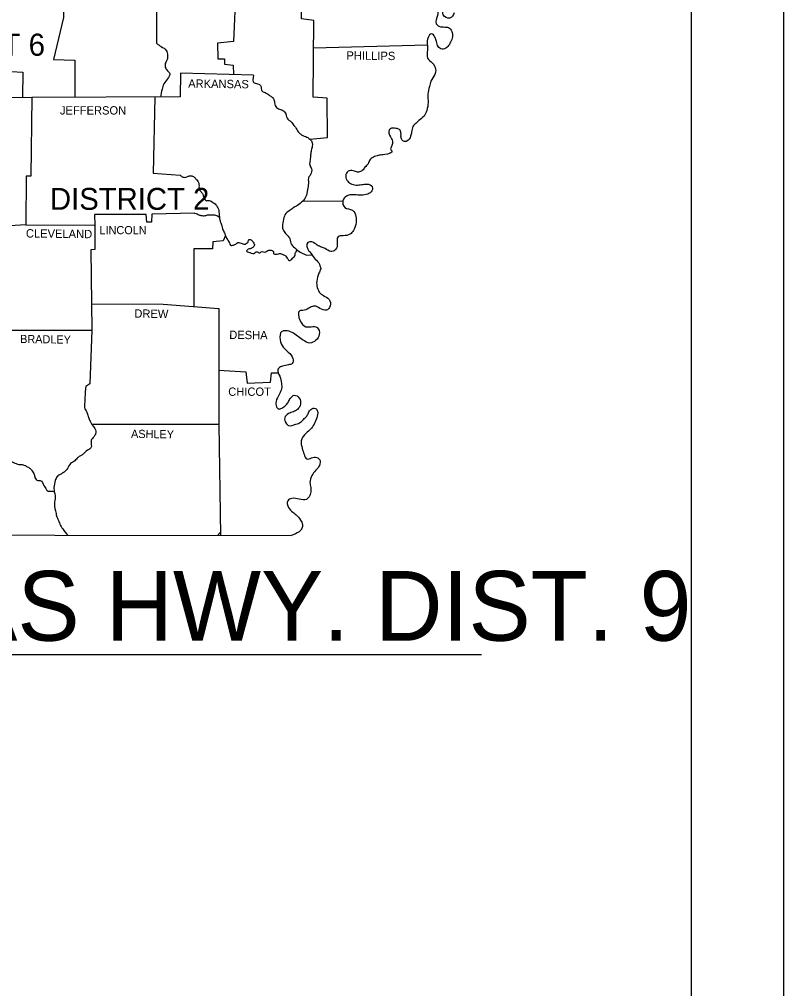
# Model space of a CAD drawing. Extents: x 19118 to 454486, y 1325406 to 1693506.
# Drawn here: x 26699 to 27093, y 1326542 to 1327042 of the extents above; entities that cross this region are included whole.
import ezdxf

# ---------------------------------------------------------------- set-up
doc = ezdxf.new("R2010")
doc.units = 0
for name, color, linetype in [('S_CURB', 7, 'Continuous'), ('S_EDGE_PAVEMENT', 7, 'Continuous'), ('S_SHOULDER', 7, 'Continuous')]:
    doc.layers.add(name, color=color, linetype=linetype)

msp = doc.modelspace()

# ---------------------------------------------------------------- linework, layer by layer
at = {"layer": 'S_CURB'}
for p, q in [((26844.86, 1326948.38), (26865.56, 1326948.58)), ((26435.93, 1326714.21), (26937.16, 1326714.21))]:
    msp.add_line(p, q, dxfattribs=at)
for points in [[(26754.87, 1327086.48), (26755.06, 1327068.58), (26769.16, 1327068.28), (26769.26, 1327029.88)], [(26715.37, 1327081.88), (26721.17, 1327081.48), (26721.27, 1327043.28), (26716.07, 1327021.58), (26727.17, 1327021.08), (26727.06, 1327001.97)], [(26848.46, 1326980.38), (26857.56, 1326981.18), (26857.46, 1327001.48), (26850.16, 1327001.98), (26850.56, 1327041.68), (26844.26, 1327042.58), (26844.06, 1327069.28), (26929.36, 1327069.88)], [(26810.26, 1327058.18), (26809.06, 1327030.78), (26800.86, 1327029.88), (26801.06, 1327021.78), (26804.36, 1327021.88), (26804.46, 1327019.08), (26808.96, 1327018.58), (26809.11, 1327013.76)], [(26638.17, 1327056.88), (26649.37, 1327056.18), (26648.97, 1327043.68), (26662.07, 1327043.18), (26662.27, 1327032.28), (26668.47, 1327031.78), (26668.47, 1327029.88), (26674.27, 1327029.48), (26674.47, 1327022.48), (26687.67, 1327022.48), (26688.07, 1327015.58), (26700.27, 1327014.98), (26700.17, 1327001.98)], [(26850.42, 1327027.58), (26909.17, 1327029.03)], [(26819.46, 1327013.48), (26781.66, 1327014.48), (26781.46, 1327002.18), (26704.97, 1327001.88)], [(26647.37, 1326988.68), (26652.97, 1326989.48), (26653.37, 1326992.88), (26656.67, 1326993.48), (26656.87, 1326995.48), (26680.17, 1326996.18), (26681.07, 1327002.28), (26704.97, 1327001.88)], [(26704.97, 1327001.88), (26704.37, 1326961.28), (26702.07, 1326961.18), (26701.77, 1326936.08)], [(26768.4, 1327002.13), (26767.56, 1326962.88), (26781.46, 1326961.78)], [(26788.87, 1326942.09), (26766.83, 1326941.55), (26766.66, 1326937.48), (26764.36, 1326937.48), (26763.96, 1326941.38), (26737.37, 1326941.38), (26737.4, 1326935.88)], [(26701.77, 1326936.08), (26687.93, 1326935.23)], [(26701.77, 1326936.08), (26737.17, 1326935.88)], [(26737.4, 1326935.88), (26737.47, 1326923.38), (26735.37, 1326923.28), (26735.97, 1326881.78)], [(26804.96, 1326930.58), (26803.76, 1326927.88), (26798.46, 1326927.38), (26798.16, 1326923.78), (26788.66, 1326923.78), (26788.56, 1326893.88)], [(26841.86, 1326923.18), (26843.54, 1326921.93), (26846.7, 1326920.44), (26849.49, 1326920.53)], [(26735.67, 1326895.38), (26772.76, 1326895.08), (26801.56, 1326892.88)], [(26801.56, 1326892.88), (26801.56, 1326833.09), (26802.36, 1326775.59)], [(26690.77, 1326881.68), (26735.97, 1326881.78)], [(26735.97, 1326881.78), (26734.97, 1326853.99), (26732.77, 1326852.59)], [(26801.56, 1326861.01), (26815.46, 1326860.19), (26816.06, 1326854.39), (26828.16, 1326854.79), (26828.66, 1326859.69), (26832.48, 1326859.68)], [(26472.17, 1326857.09), (26472.37, 1326776.19), (26838.86, 1326775.59)], [(26736.57, 1326833.19), (26801.56, 1326833.19)], [(26717.67, 1326805.69), (26718.47, 1326806.49)], [(26800.76, 1326775.69), (26802.26, 1326777.19)]]:
    msp.add_lwpolyline(points, dxfattribs=at)
for points in [[(26923.06, 1327045.68), (26920.76, 1327042.78), (26917.36, 1327044.58), (26917.36, 1327046.98), (26917.86, 1327049.48), (26916.66, 1327051.08), (26914.56, 1327050.38), (26914.56, 1327047.28), (26914.36, 1327044.28), (26913.76, 1327039.98), (26915.16, 1327038.68), (26918.36, 1327038.28), (26920.66, 1327037.68), (26922.06, 1327035.38), (26921.96, 1327032.58), (26920.86, 1327029.88), (26919.26, 1327027.68), (26916.76, 1327026.88), (26914.76, 1327028.18), (26913.96, 1327030.78), (26913.06, 1327033.08), (26911.36, 1327034.78), (26909.56, 1327032.88), (26909.16, 1327029.38), (26909.26, 1327026.38), (26909.26, 1327022.28), (26911.86, 1327019.58), (26913.46, 1327016.48), (26912.96, 1327013.68), (26911.06, 1327010.38), (26910.26, 1327007.48), (26909.46, 1327003.58), (26909.56, 1326999.28), (26908.86, 1326995.08), (26907.46, 1326992.28), (26904.86, 1326989.98), (26903.16, 1326988.48), (26901.76, 1326986.98), (26901.06, 1326983.98), (26900.56, 1326981.88), (26898.66, 1326979.38), (26897.16, 1326979.18), (26895.96, 1326980.18), (26895.56, 1326981.88), (26895.56, 1326983.58), (26894.76, 1326985.28), (26892.26, 1326985.98), (26890.26, 1326985.88), (26889.36, 1326984.48), (26890.66, 1326980.58), (26891.16, 1326978.08), (26890.46, 1326974.68), (26890.86, 1326974.28), (26887.26, 1326972.38), (26884.36, 1326972.08), (26881.96, 1326971.38), (26879.66, 1326969.88), (26878.56, 1326967.68), (26876.96, 1326965.88), (26875.56, 1326964.18), (26873.66, 1326963.38), (26871.56, 1326963.78), (26868.76, 1326964.08), (26867.16, 1326962.08), (26867.66, 1326959.18), (26869.56, 1326957.48), (26872.36, 1326956.68), (26875.26, 1326956.88), (26878.06, 1326957.18), (26880.66, 1326955.78), (26880.16, 1326953.08), (26877.66, 1326951.78), (26873.96, 1326951.38), (26870.96, 1326951.68), (26867.36, 1326950.88), (26865.56, 1326948.58), (26866.56, 1326945.08), (26870.46, 1326943.68), (26872.26, 1326940.38), (26872.36, 1326937.28), (26871.06, 1326933.18), (26869.26, 1326931.28), (26865.76, 1326930.48), (26863.06, 1326929.98), (26862.66, 1326925.38), (26861.46, 1326923.08), (26859.36, 1326922.38), (26856.36, 1326923.88), (26854.56, 1326924.58), (26852.36, 1326925.58), (26849.56, 1326927.28), (26847.46, 1326926.98), (26848.06, 1326922.58), (26848.26, 1326922.38), (26850.66, 1326919.08), (26853.06, 1326916.48), (26854.16, 1326913.38)], [(26769.26, 1327029.88), (26771.76, 1327028.18), (26774.36, 1327026.18), (26775.06, 1327023.48), (26774.86, 1327021.58), (26774.06, 1327019.98), (26773.86, 1327017.48), (26775.06, 1327015.68), (26776.16, 1327014.18), (26775.06, 1327011.48), (26773.16, 1327008.98), (26772.16, 1327006.18), (26771.46, 1327001.98)], [(26819.46, 1327013.48), (26819.76, 1327009.38), (26822.16, 1327008.78), (26823.16, 1327007.68), (26823.66, 1327005.38), (26825.36, 1327004.38), (26827.66, 1327002.98), (26829.06, 1327001.98), (26830.06, 1327000.38), (26830.66, 1326997.78), (26832.26, 1326996.08), (26834.46, 1326995.28), (26836.06, 1326993.38), (26837.06, 1326990.68), (26838.66, 1326989.48), (26840.26, 1326987.38), (26841.06, 1326986.48), (26842.46, 1326984.08), (26843.86, 1326982.88), (26844.86, 1326982.18), (26846.46, 1326981.68), (26848.46, 1326980.38), (26849.76, 1326978.38), (26849.76, 1326976.88), (26849.26, 1326974.58), (26848.86, 1326972.18), (26848.66, 1326969.48), (26848.46, 1326967.08), (26849.36, 1326965.08), (26848.86, 1326962.08), (26847.86, 1326960.48), (26847.76, 1326958.28), (26847.46, 1326954.98), (26847.06, 1326953.08), (26846.16, 1326949.98), (26844.86, 1326948.38)], [(26781.46, 1326961.78), (26782.96, 1326960.78), (26785.06, 1326960.88), (26786.46, 1326961.48), (26787.56, 1326961.38), (26789.06, 1326960.48), (26790.06, 1326959.28), (26790.76, 1326958.38), (26791.26, 1326956.98), (26791.26, 1326955.68), (26791.76, 1326953.88), (26792.36, 1326953.18), (26793.16, 1326951.88), (26793.66, 1326950.68), (26793.96, 1326949.88), (26795.06, 1326948.58), (26796.06, 1326948.68), (26796.96, 1326948.58), (26798.16, 1326947.88), (26799.96, 1326946.48), (26800.26, 1326946.08), (26801.46, 1326943.48), (26801.66, 1326941.88), (26801.86, 1326939.78), (26802.26, 1326937.78), (26803.06, 1326935.58), (26803.46, 1326934.08), (26804.36, 1326931.98), (26804.96, 1326930.58), (26805.76, 1326928.78), (26806.96, 1326926.78), (26807.46, 1326925.58), (26809.16, 1326925.68), (26810.36, 1326926.18), (26811.26, 1326926.98), (26812.36, 1326926.88), (26813.56, 1326926.48), (26815.16, 1326926.18), (26816.16, 1326926.78), (26816.66, 1326927.18), (26816.76, 1326928.08), (26817.66, 1326928.58), (26818.66, 1326927.88), (26819.76, 1326926.28), (26819.76, 1326925.28), (26819.36, 1326924.68), (26818.06, 1326923.88), (26816.26, 1326923.28), (26815.76, 1326922.58), (26817.46, 1326921.78), (26820.16, 1326921.58), (26820.86, 1326922.18), (26822.66, 1326921.68), (26823.36, 1326922.18), (26825.76, 1326922.08), (26826.86, 1326922.88), (26829.06, 1326922.78), (26829.76, 1326922.28), (26829.76, 1326921.38), (26831.56, 1326920.98), (26832.86, 1326921.28), (26834.56, 1326920.78), (26836.06, 1326919.98), (26836.86, 1326918.88), (26837.86, 1326917.68), (26838.76, 1326917.98), (26839.46, 1326918.88), (26840.96, 1326920.48), (26840.96, 1326921.48), (26841.36, 1326922.18), (26841.86, 1326923.18)], [(26844.86, 1326948.38), (26842.06, 1326946.08), (26840.26, 1326945.08), (26838.36, 1326943.68), (26836.06, 1326941.98), (26834.96, 1326939.08), (26834.36, 1326935.08), (26835.16, 1326932.68), (26836.96, 1326930.58), (26838.16, 1326928.88), (26839.06, 1326925.88), (26841.26, 1326923.78), (26841.86, 1326923.18)], [(26788.87, 1326942.09), (26789.06, 1326942.08), (26790.36, 1326941.78), (26791.46, 1326941.18), (26792.26, 1326940.98), (26793.46, 1326940.78), (26794.46, 1326940.88), (26796.16, 1326941.28), (26797.16, 1326941.28), (26798.76, 1326941.28), (26799.76, 1326941.18), (26801.81, 1326940.12)], [(26854.16, 1326913.38), (26853.16, 1326911.08), (26852.06, 1326907.08), (26852.36, 1326903.68), (26853.86, 1326900.78), (26856.26, 1326899.18), (26858.86, 1326896.88), (26858.66, 1326893.38), (26857.16, 1326892.08), (26853.66, 1326892.98), (26850.96, 1326894.18), (26848.66, 1326893.48), (26845.56, 1326891.98), (26843.26, 1326891.68), (26843.36, 1326886.88), (26846.46, 1326883.48), (26849.16, 1326883.48), (26852.26, 1326883.08), (26853.36, 1326879.49), (26851.56, 1326876.49), (26848.56, 1326874.99), (26844.76, 1326876.79), (26842.06, 1326878.69), (26839.36, 1326880.49), (26835.96, 1326881.38), (26834.06, 1326880.99), (26833.16, 1326876.79), (26834.76, 1326872.99), (26837.36, 1326870.39), (26839.76, 1326866.99), (26839.36, 1326864.49), (26837.56, 1326863.79), (26834.36, 1326863.09), (26832.46, 1326862.09), (26831.96, 1326861.29), (26832.96, 1326857.89), (26833.86, 1326854.19), (26833.86, 1326851.39), (26832.76, 1326848.79), (26831.06, 1326844.79), (26831.26, 1326842.19), (26832.46, 1326840.99), (26833.96, 1326841.39), (26835.96, 1326842.79), (26837.26, 1326844.39), (26838.36, 1326846.39), (26840.46, 1326848.09), (26843.06, 1326846.59), (26843.66, 1326843.49), (26842.16, 1326840.79), (26840.06, 1326839.59), (26837.46, 1326838.59), (26835.56, 1326836.39), (26836.06, 1326833.79), (26837.56, 1326832.39), (26841.26, 1326833.09), (26843.76, 1326834.19), (26845.16, 1326835.59), (26846.86, 1326837.29), (26847.76, 1326838.99), (26849.06, 1326840.79), (26851.36, 1326841.29), (26852.46, 1326839.79), (26852.06, 1326836.39), (26850.66, 1326833.19), (26848.76, 1326830.49), (26846.66, 1326828.59), (26844.06, 1326824.49), (26844.56, 1326820.69), (26845.56, 1326817.59), (26846.96, 1326815.19), (26849.36, 1326815.69), (26852.06, 1326815.99), (26853.66, 1326814.69), (26853.46, 1326811.89), (26851.46, 1326809.19), (26849.56, 1326806.59), (26848.56, 1326802.99), (26848.96, 1326800.49), (26848.96, 1326798.19), (26848.16, 1326795.69), (26846.76, 1326794.29), (26843.06, 1326794.39), (26839.16, 1326794.79), (26837.06, 1326793.59), (26837.46, 1326790.19), (26839.76, 1326787.69), (26841.36, 1326786.39), (26843.66, 1326783.59), (26844.66, 1326781.29), (26844.36, 1326779.29), (26842.96, 1326777.59), (26838.86, 1326775.59)], [(26732.77, 1326852.59), (26732.47, 1326849.49), (26732.37, 1326846.59), (26732.17, 1326843.79), (26732.17, 1326841.69), (26733.37, 1326839.39), (26734.07, 1326837.19), (26734.77, 1326835.29), (26736.17, 1326832.79), (26737.47, 1326830.89), (26737.87, 1326828.19), (26737.07, 1326826.79), (26735.57, 1326824.69), (26735.47, 1326820.89), (26733.67, 1326819.69), (26731.37, 1326817.69), (26730.07, 1326816.79), (26728.67, 1326815.89), (26727.17, 1326814.29), (26724.97, 1326812.79), (26723.37, 1326810.29), (26721.57, 1326808.39), (26720.07, 1326807.39), (26717.97, 1326806.09), (26717.07, 1326804.09), (26716.37, 1326800.39), (26716.67, 1326797.69), (26717.07, 1326795.29), (26716.57, 1326792.29), (26717.07, 1326788.99), (26717.57, 1326786.39), (26718.37, 1326784.09), (26719.47, 1326781.49), (26720.87, 1326779.09), (26723.5, 1326775.77)], [(26633.07, 1326829.49), (26634.67, 1326830.59), (26636.17, 1326831.19), (26637.67, 1326830.89), (26639.27, 1326830.69), (26640.67, 1326830.89), (26642.47, 1326830.59), (26643.97, 1326829.69), (26645.67, 1326828.99), (26647.37, 1326828.99), (26648.87, 1326828.99), (26650.17, 1326828.09), (26652.57, 1326828.19), (26654.57, 1326828.99), (26656.57, 1326829.59), (26659.27, 1326829.89), (26661.67, 1326828.19), (26663.37, 1326826.79), (26664.77, 1326825.19), (26665.77, 1326823.39), (26666.87, 1326822.39), (26668.67, 1326821.69), (26670.07, 1326821.39), (26671.77, 1326820.89), (26672.67, 1326820.49), (26673.47, 1326818.59), (26674.77, 1326815.99), (26677.27, 1326815.09), (26680.37, 1326816.29), (26682.87, 1326816.99), (26684.67, 1326817.59), (26685.77, 1326817.99), (26686.77, 1326818.09), (26686.47, 1326818.29), (26687.67, 1326818.59), (26688.77, 1326817.79), (26689.47, 1326816.69), (26690.67, 1326815.09), (26691.77, 1326813.69), (26692.87, 1326813.19), (26693.97, 1326813.79), (26695.47, 1326813.29), (26696.77, 1326812.79), (26698.27, 1326812.39), (26699.57, 1326812.29), (26701.27, 1326811.89), (26702.57, 1326811.19), (26703.77, 1326810.49), (26704.97, 1326809.19), (26706.17, 1326807.19), (26706.57, 1326805.59), (26707.97, 1326803.99), (26709.27, 1326803.99), (26711.17, 1326801.39), (26711.87, 1326800.39), (26713.37, 1326798.59), (26714.47, 1326798.59), (26716.57, 1326798.19)]]:
    msp.add_spline(points, degree=3, dxfattribs=at)
at = {"layer": 'S_EDGE_PAVEMENT'}
msp.add_lwpolyline([(23759.74, 1327539.29), (27093.14, 1327539.29), (27093.14, 1325405.92), (23759.74, 1325405.92)], close=True, dxfattribs=at)
at = {"layer": 'S_SHOULDER'}
msp.add_line((27045.61, 1325445.75), (27045.61, 1327500.35), dxfattribs=at)

# ---------------------------------------------------------------- texts
at = {"layer": 'S_CURB'}
for s, height, p in [('DISTRICT 6', 11.4, (26628.75, 1327023.45)), ('JEFFERSON', 4.3, (26719.47, 1326993.08)), ('DISTRICT 2', 11.3, (26714.31, 1326943.87)), ('LINCOLN', 4.2, (26739.87, 1326931.28)), ('CHICOT', 4.3, (26806.36, 1326847.79)), ('ARKANSAS HWY. DIST. 9', 36.036, (26467.18, 1326721.3))]:
    msp.add_text(s, height=height, dxfattribs=at).set_placement(p)
for s, height, rotation, p in [('PHILLIPS', 4.3, 359.3179, (26867.36, 1327021.48)), ('ARKANSAS', 4.3, 359.2678, (26785.66, 1327006.98)), ('CLEVELAND', 4.301, 359.3376, (26701.87, 1326929.58)), ('DREW', 4.299, 359.2258, (26757.86, 1326888.18)), ('BRADLEY', 4.199, 359.1449, (26698.87, 1326875.09)), ('DESHA', 4.299, 359.3704, (26806.86, 1326877.19)), ('ASHLEY', 4.201, 359.2361, (26756.16, 1326826.09))]:
    msp.add_text(s, height=height, rotation=rotation, dxfattribs=at).set_placement(p)

doc.saveas('drawing.dxf')
